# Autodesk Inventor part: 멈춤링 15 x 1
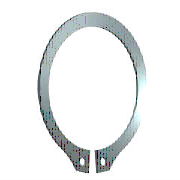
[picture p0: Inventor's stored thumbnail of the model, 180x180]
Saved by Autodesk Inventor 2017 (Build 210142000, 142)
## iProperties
IsCustomPart: 1
Created: 2012-02
Part Number: 멈춤링 15 x 1
Material: 강철, 연강
Description: 리테이닝 링(C형)
Document SubType Name: Modeling
Standard: KS B 1336
Designer: mduedu
Standards Organization: KS
Language: ko-KR
Size Designation: 15 x 1
Categories: <MemberInstance><Categories><Category DisplayName="샤프트 부품" InternalName="7f7aeb1f-a693-4053-b835-cee3144e0d98" Mnemonic="SHFT"><Category DisplayName="써클립" Inter
Density: 1 g/cm^3
Appearance: 파란색 - 벽 페인트 - 광택
Author: mduedu
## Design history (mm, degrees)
sketch "스케치1"
  geometry: L1 (-6, 0)-(6, 0) reference; L2 (0, 20.189)-(0, -80.536) reference; L3 (-48.09, 0)-(48.09, 0) reference; L4 (-0.425, -14.637)-(-0.425, -18.137); L5 (-0.425, -6.54)-(-0.425, -13.29); L6 (-2.795, 2.1)-(3.672, 2.1); L7 (0.425, -6.54)-(0.425, -13.29); L8 (0.425, -14.637)-(0.425, -18.137); C1 r 0.85 at (-1.7, -16.283); C2 r 0.85 at (1.7, -16.283); A1 r 7.15 centre (0, -7.5) between (0.425, -14.637) and (-0.425, -14.637); A2 r 9.075 centre (0, -6.975) between (4.291, -14.971) and (-4.291, -14.971); A3 r 10.646 centre (0, -7.5) between (-2.023, -17.952) and (-0.425, -18.137); A4 r 1.7 centre (-1.7, -16.283) between (-3.397, -16.376) and (-2.023, -17.952); A5 r 1.7 centre (-5.095, -16.469) between (-3.397, -16.376) and (-4.291, -14.971); A6 r 1.7 centre (5.095, -16.469) between (4.291, -14.971) and (3.397, -16.376); A7 r 1.7 centre (1.7, -16.283) between (2.023, -17.952) and (3.397, -16.376); A8 r 10.646 centre (0, -7.5) between (0.425, -18.137) and (2.023, -17.952)
  constraints: 16 point on circle, 12 end point, 10 centre point, 9 symmetric about line, 5 point on line, 4 tangent, 3 coincident, 2 horizontal, 1 perpendicular, 1 vertical, 5 other
  dimensions: "d0" = 14.3 diameter of A1 (= ND); "d1" = 3.5 distance of L4.end L4.start (= SRB2); "d6" = 0.425 distance between parallel lines of L2 L5 (= 0.25 x SD5); "d7" = 2.1 distance between parallel lines of L6 L3 (= SRB1); "d8" = 0.525 distance of A1.centre A2.centre (= 0.25 x SRB1); "d9" = 1.7 radius of A4 (= SD5); "d10" = 1.7 radius of A5 (= SD5); "d11" = 1.275 distance from line of L4 A4.centre (= 0.75 x SD5); "d12" = 1.7 diameter of C1 (= SD5); "d13" = 1.7 diameter of C2 (= SD5); "d14" = 7.5 distance from line of A1.centre L1 (= 0.5 x WD)
extrude "본체" new body sketch "스케치1" distance "d2" = 1 (= SD); taper "d3" = 0 deg
workaxis "Work Axis1"
workplane "Work Plane1"
body "Solid1"
other parameters: "WD" = 15 (= WDMIN) [user parameter; used in 1 equation term], "SD" = 1 [user parameter; used in 1 equation term], "SRB1" = 2.1 [user parameter; used in 2 equation terms], "ND" = 14.3 [user parameter; used in 1 equation term], "SRB2" = 3.5 [user parameter; used in 1 equation term], "SD5" = 1.7 [user parameter; used in 6 equation terms], "d15" = 0, "d16" = 0, "d17" = 0, "d41" = 0, "d42" = 0, "WDMIN" = 15 [user parameter; used in 1 equation term], "SD3" = 13.8 [user parameter], "WDMAX" = 16 [user parameter]
